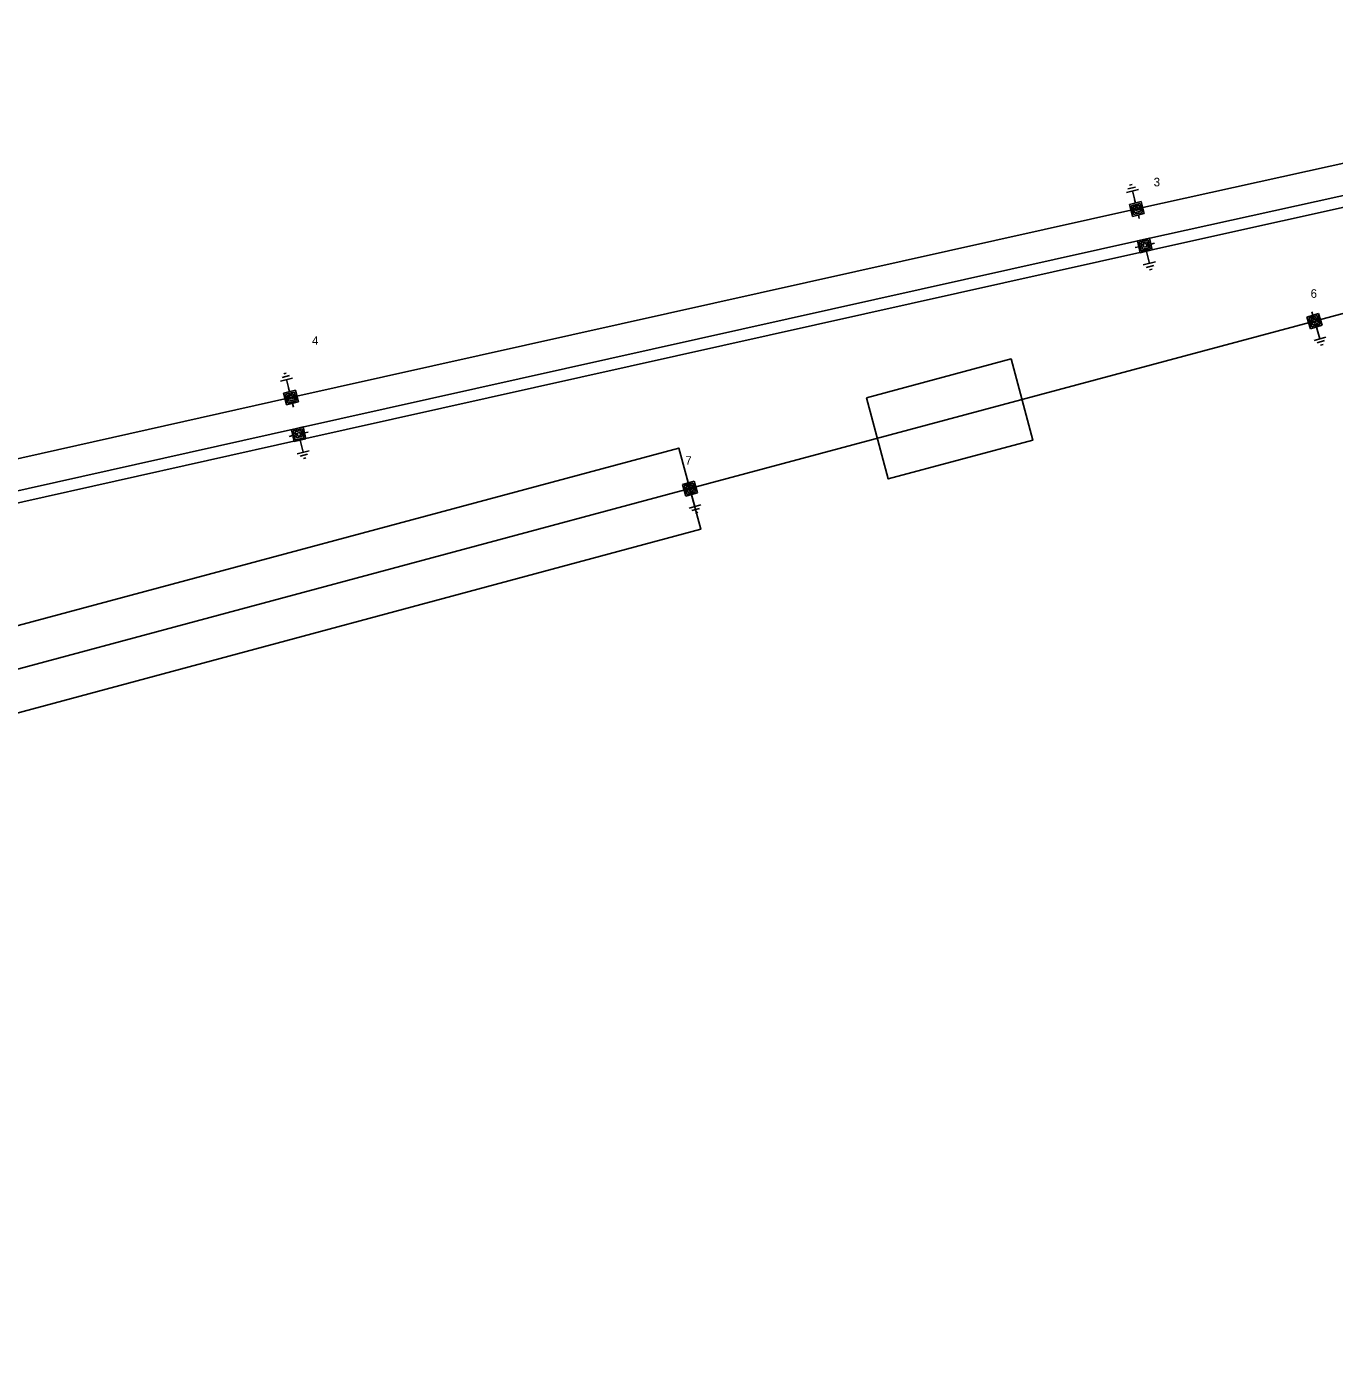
# Model space of a CAD drawing. Extents: x -763667 to -762498, y -1153000 to -1152000.
# Drawn here: x -763137.4 to -762873.3, y -1153000 to -1152729.9 of the extents above; entities that cross this region are included whole.
import ezdxf

# ---------------------------------------------------------------- set-up
doc = ezdxf.new("R2010")
doc.units = 0
for name, color, linetype in [('Vrstva 1', 7, 'Continuous'), ('Vrstva 13', 7, 'Continuous'), ('Vrstva 14', 7, 'Continuous'), ('Vrstva 15', 7, 'Continuous'), ('Vrstva 35', 7, 'Continuous')]:
    doc.layers.add(name, color=color, linetype=linetype)

msp = doc.modelspace()

# ---------------------------------------------------------------- linework, layer by layer
at = {"layer": 'Vrstva 1'}
for points in [[(-763515.95, -1153000), (-763408.81, -1152935.67), (-763253.73, -1152842.91), (-763084.04, -1152804.87), (-762913.18, -1152766.77), (-762746.61, -1152729.95), (-762623.2, -1152759.36)], [(-763503.85, -1153000), (-763406.01, -1152941.37), (-763250.71, -1152848.67), (-763082.9, -1152811.11), (-762911.77, -1152772.97), (-762745.04, -1152736.18), (-762624.04, -1152762.13)], [(-763499.11, -1153000), (-763404.8, -1152943.47), (-763250.15, -1152850.99), (-763082.25, -1152813.42), (-762911.4, -1152775.32), (-762745.76, -1152738.55), (-762671.17, -1152758.11)], [(-762675.53, -1152765.62), (-762747.37, -1152754.51), (-762877.29, -1152789.43), (-763003.47, -1152823.28), (-763146.35, -1152861.67), (-763295.27, -1152929.58), (-763425.09, -1152988.74), (-763449.87, -1153000)]]:
    msp.add_lwpolyline(points, dxfattribs=at)
at = {"layer": 'Vrstva 13'}
for points in [[(-762913.476, -1152765.582), (-762913.657, -1152764.856)], [(-762914.668, -1152765.879), (-762912.285, -1152765.285)], [(-762914.074, -1152768.263), (-762914.668, -1152765.879)], [(-762914.291, -1152766.122), (-762912.504, -1152765.676)], [(-762913.845, -1152767.91), (-762914.291, -1152766.122)], [(-762911.69, -1152767.669), (-762914.074, -1152768.263)], [(-762913.924, -1152766.327), (-762912.732, -1152766.029)], [(-762913.626, -1152767.519), (-762913.924, -1152766.327)], [(-762912.058, -1152767.464), (-762913.845, -1152767.91)], [(-762912.435, -1152767.222), (-762913.626, -1152767.519)], [(-762913.561, -1152766.513), (-762912.965, -1152766.365)], [(-762913.412, -1152767.109), (-762913.561, -1152766.513)], [(-762912.816, -1152766.961), (-762913.412, -1152767.109)], [(-762912.965, -1152766.365), (-762912.816, -1152766.961)], [(-762912.732, -1152766.029), (-762912.435, -1152767.222)], [(-762912.504, -1152765.676), (-762912.058, -1152767.464)], [(-762912.285, -1152765.285), (-762911.69, -1152767.669)], [(-762912.882, -1152767.966), (-762912.701, -1152768.692)], [(-762913.048, -1152773.22), (-762910.653, -1152772.668)], [(-762912.495, -1152775.614), (-762913.048, -1152773.22)], [(-762912.698, -1152773.455), (-762910.903, -1152773.04)], [(-762910.903, -1152773.04), (-762910.488, -1152774.835)], [(-762910.653, -1152772.668), (-762910.101, -1152775.061)], [(-762912.771, -1152774.417), (-762913.5, -1152774.585)], [(-762912.283, -1152775.25), (-762912.698, -1152773.455)], [(-762910.101, -1152775.061), (-762912.495, -1152775.614)], [(-762912.311, -1152773.681), (-762911.114, -1152773.404)], [(-762912.035, -1152774.877), (-762912.311, -1152773.681)], [(-762910.488, -1152774.835), (-762912.283, -1152775.25)], [(-762910.837, -1152774.601), (-762912.035, -1152774.877)], [(-762911.905, -1152773.902), (-762911.307, -1152773.764)], [(-762911.767, -1152774.5), (-762911.905, -1152773.902)], [(-762911.169, -1152774.362), (-762911.767, -1152774.5)], [(-762911.307, -1152773.764), (-762911.169, -1152774.362)], [(-762911.114, -1152773.404), (-762910.837, -1152774.601)], [(-762910.377, -1152773.864), (-762909.648, -1152773.696)], [(-762878.822, -1152788.619), (-762876.473, -1152787.901)], [(-762878.104, -1152790.969), (-762878.822, -1152788.619)], [(-762878.433, -1152788.841), (-762876.671, -1152788.303)], [(-762877.894, -1152790.603), (-762878.433, -1152788.841)], [(-762878.055, -1152789.027), (-762876.881, -1152788.667)], [(-762877.696, -1152790.202), (-762878.055, -1152789.027)], [(-762877.648, -1152788.26), (-762877.866, -1152787.544)], [(-762877.683, -1152789.194), (-762877.096, -1152789.014)], [(-762877.503, -1152789.781), (-762877.683, -1152789.194)], [(-762877.096, -1152789.014), (-762876.916, -1152789.602)], [(-762876.881, -1152788.667), (-762876.521, -1152789.843)], [(-762876.671, -1152788.303), (-762876.132, -1152790.065)], [(-762876.473, -1152787.901), (-762875.755, -1152790.25)], [(-762875.755, -1152790.25), (-762878.104, -1152790.969)], [(-762876.132, -1152790.065), (-762877.894, -1152790.603)], [(-762876.521, -1152789.843), (-762877.696, -1152790.202)], [(-762876.916, -1152789.602), (-762877.503, -1152789.781)], [(-762876.929, -1152790.609), (-762876.711, -1152791.325)], [(-763085.528, -1152803.979), (-763083.145, -1152803.385)], [(-763084.934, -1152806.363), (-763085.528, -1152803.979)], [(-763085.151, -1152804.222), (-763083.364, -1152803.776)], [(-763084.705, -1152806.01), (-763085.151, -1152804.222)], [(-763084.784, -1152804.427), (-763083.592, -1152804.129)], [(-763084.486, -1152805.619), (-763084.784, -1152804.427)], [(-763082.918, -1152805.564), (-763084.705, -1152806.01)], [(-763084.336, -1152803.682), (-763084.517, -1152802.956)], [(-763083.295, -1152805.322), (-763084.486, -1152805.619)], [(-763084.421, -1152804.613), (-763083.825, -1152804.465)], [(-763084.272, -1152805.209), (-763084.421, -1152804.613)], [(-763083.676, -1152805.061), (-763084.272, -1152805.209)], [(-763083.825, -1152804.465), (-763083.676, -1152805.061)], [(-763083.592, -1152804.129), (-763083.295, -1152805.322)], [(-763083.364, -1152803.776), (-763082.918, -1152805.564)], [(-763083.145, -1152803.385), (-763082.55, -1152805.769)], [(-763082.55, -1152805.769), (-763084.934, -1152806.363)], [(-763083.742, -1152806.066), (-763083.561, -1152806.792)], [(-763083.958, -1152811.37), (-763081.563, -1152810.818)], [(-763081.563, -1152810.818), (-763081.011, -1152813.211)], [(-763083.681, -1152812.567), (-763084.41, -1152812.735)], [(-763083.405, -1152813.764), (-763083.958, -1152811.37)], [(-763083.608, -1152811.605), (-763081.813, -1152811.19)], [(-763083.193, -1152813.4), (-763083.608, -1152811.605)], [(-763081.011, -1152813.211), (-763083.405, -1152813.764)], [(-763083.221, -1152811.831), (-763082.024, -1152811.554)], [(-763082.945, -1152813.027), (-763083.221, -1152811.831)], [(-763081.398, -1152812.985), (-763083.193, -1152813.4)], [(-763081.747, -1152812.751), (-763082.945, -1152813.027)], [(-763082.815, -1152812.052), (-763082.217, -1152811.914)], [(-763082.677, -1152812.65), (-763082.815, -1152812.052)], [(-763082.079, -1152812.512), (-763082.677, -1152812.65)], [(-763082.217, -1152811.914), (-763082.079, -1152812.512)], [(-763082.024, -1152811.554), (-763081.747, -1152812.751)], [(-763081.813, -1152811.19), (-763081.398, -1152812.985)], [(-763081.287, -1152812.014), (-763080.558, -1152811.846)], [(-763004.988, -1152822.442), (-763002.627, -1152821.765)], [(-763003.808, -1152822.103), (-763004.014, -1152821.384)], [(-763002.627, -1152821.765), (-763001.95, -1152824.127)], [(-763004.311, -1152824.804), (-763004.988, -1152822.442)], [(-763004.603, -1152822.671), (-763002.832, -1152822.163)], [(-763004.095, -1152824.442), (-763004.603, -1152822.671)], [(-763001.95, -1152824.127), (-763004.311, -1152824.804)], [(-763004.229, -1152822.863), (-763003.048, -1152822.524)], [(-763003.89, -1152824.044), (-763004.229, -1152822.863)], [(-763002.324, -1152823.934), (-763004.095, -1152824.442)], [(-763002.709, -1152823.706), (-763003.89, -1152824.044)], [(-763003.86, -1152823.037), (-763003.269, -1152822.867)], [(-763003.69, -1152823.627), (-763003.86, -1152823.037)], [(-763003.1, -1152823.458), (-763003.69, -1152823.627)], [(-763003.269, -1152822.867), (-763003.1, -1152823.458)], [(-763003.131, -1152824.465), (-763002.924, -1152825.184)], [(-763003.048, -1152822.524), (-763002.709, -1152823.706)], [(-763002.832, -1152822.163), (-763002.324, -1152823.934)]]:
    msp.add_lwpolyline(points, dxfattribs=at)
at = {"layer": 'Vrstva 15'}
for points in [[(-762914.985, -1152762.719), (-762913.457, -1152762.338)], [(-762914.65, -1152761.987), (-762914.392, -1152761.922)], [(-762914.392, -1152761.922), (-762914.144, -1152761.86)], [(-762915.303, -1152763.438), (-762912.877, -1152762.833)], [(-762913.485, -1152765.561), (-762914.09, -1152763.135)], [(-762911.265, -1152775.349), (-762910.66, -1152777.775)], [(-762909.447, -1152777.472), (-762911.873, -1152778.077)], [(-762909.765, -1152778.191), (-762911.293, -1152778.572)], [(-762910.358, -1152778.988), (-762910.606, -1152779.05)], [(-762910.1, -1152778.923), (-762910.358, -1152778.988)], [(-762876.922, -1152790.621), (-762876.191, -1152793.012)], [(-762874.996, -1152792.647), (-762877.386, -1152793.378)], [(-762875.275, -1152793.381), (-762876.782, -1152793.841)], [(-762875.825, -1152794.208), (-762876.07, -1152794.282)], [(-762875.571, -1152794.13), (-762875.825, -1152794.208)], [(-763085.51, -1152800.087), (-763085.252, -1152800.022)], [(-763085.252, -1152800.022), (-763085.004, -1152799.96)], [(-763086.163, -1152801.538), (-763083.737, -1152800.933)], [(-763085.845, -1152800.819), (-763084.317, -1152800.438)], [(-763084.345, -1152803.661), (-763084.95, -1152801.235)], [(-763082.175, -1152813.499), (-763081.57, -1152815.925)], [(-763080.357, -1152815.622), (-763082.783, -1152816.227)], [(-763080.675, -1152816.341), (-763082.203, -1152816.722)], [(-763081.268, -1152817.138), (-763081.516, -1152817.2)], [(-763081.01, -1152817.073), (-763081.268, -1152817.138)], [(-763003.123, -1152824.478), (-763002.434, -1152826.881)], [(-763001.232, -1152826.536), (-763003.635, -1152827.226)], [(-763001.525, -1152827.265), (-763003.039, -1152827.7)], [(-763002.089, -1152828.083), (-763002.335, -1152828.153)], [(-763001.834, -1152828.009), (-763002.089, -1152828.083)]]:
    msp.add_lwpolyline(points, dxfattribs=at)
at = {"layer": 'Vrstva 35'}
msp.add_lwpolyline([(-762967.81, -1152804.91), (-762963.41, -1152821.33), (-762934.17, -1152813.49), (-762938.58, -1152797.07)], close=True, dxfattribs=at)
msp.add_lwpolyline([(-763429.5, -1153000), (-763291.74, -1152937.31), (-763143.46, -1152869.7), (-763001.24, -1152831.48), (-763005.7, -1152815.08), (-763149.24, -1152853.64), (-763298.8, -1152921.85), (-763470.55, -1153000)], dxfattribs=at)

# ---------------------------------------------------------------- texts
at = {"layer": 'Vrstva 14'}
for s, p in [('3', (-762909.79, -1152762.2)), ('6', (-762878.09, -1152784.73)), ('4', (-763079.79, -1152794.22)), ('7', (-763004.39, -1152818.46))]:
    msp.add_text(s, height=1.74, dxfattribs=at).set_placement(p)

doc.saveas('drawing.dxf')
